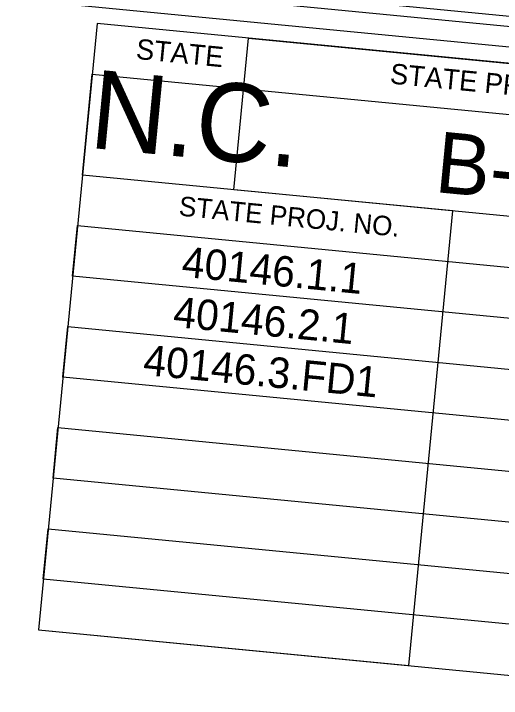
# Model space of a CAD drawing. Extents: x 2060574 to 2063008, y 912203 to 913082.
# Drawn here: x 2061449.3 to 2061521.3, y 912882.4 to 912983.6 of the extents above; entities that cross this region are included whole.
import ezdxf

# ---------------------------------------------------------------- set-up
doc = ezdxf.new("R2010")
doc.units = 0
for name, color, linetype in [('Sheet Data Field CELL', 7, 'Continuous'), ('Sheet Plot Border Inside CELL', 7, 'Continuous'), ('Sheet Title CELL', 7, 'Continuous')]:
    doc.layers.add(name, color=color, linetype=linetype)

msp = doc.modelspace()

# ---------------------------------------------------------------- linework, layer by layer
at = {"layer": 'Sheet Plot Border Inside CELL'}
msp.add_lwpolyline([(2060583.16, 912437.96), (2061578.42, 912341.76), (2061639.33, 912971.88), (2060644.07, 913068.09)], close=True, dxfattribs=at)
at = {"layer": 'Sheet Title CELL'}
for points in [[(2061625.75, 912971.65), (2060741.86, 913057.1)], [(2061622.47, 912968.96), (2060774.43, 913050.93)], [(2061625.82, 912966.23), (2061461.59, 912982.1), (2061452.93, 912892.52), (2061507.66, 912887.22), (2061514.16, 912954.41), (2061481.82, 912957.54), (2061483.99, 912979.94), (2061581.04, 912970.55)], [(2061623.66, 912943.83), (2061459.42, 912959.71), (2061460.87, 912974.64), (2061625.1, 912958.76)], [(2061622.22, 912928.9), (2061457.98, 912944.77), (2061458.7, 912952.24), (2061622.94, 912936.36)], [(2061620.77, 912913.97), (2061456.54, 912929.85), (2061457.26, 912937.31), (2061621.49, 912921.44)], [(2061619.33, 912899.04), (2061455.1, 912914.91), (2061455.82, 912922.38), (2061620.05, 912906.51)], [(2061617.89, 912884.11), (2061453.65, 912899.99), (2061454.37, 912907.45), (2061618.61, 912891.57)], [(2061452.93, 912892.52), (2061617.16, 912876.65)]]:
    msp.add_lwpolyline(points, dxfattribs=at)

# ---------------------------------------------------------------- texts
at = {"layer": 'Sheet Data Field CELL'}
for s, height, p in [('B-4944', 9, (2061511.34, 912957.22)), ('40146.1.1', 4.5, (2061473.98, 912944.7)), ('40146.2.1', 4.5, (2061472.72, 912937.29)), ('40146.3.FD1', 4.5, (2061468.29, 912930.19))]:
    msp.add_text(s, height=height, rotation=354.4787, dxfattribs=at).set_placement(p)
at = {"layer": 'Sheet Title CELL'}
for s, height, p in [('STATE', 3, (2061467.26, 912976.89)), ('STATE PROJECT REFERENCE NO.', 2.9999, (2061504.8, 912973.25)), ('N.C.', 11.61, (2061460.27, 912963.76)), ('STATE PROJ. NO.', 2.88, (2061473.59, 912953.73))]:
    msp.add_text(s, height=height, rotation=354.4787, dxfattribs=at).set_placement(p)

doc.saveas('drawing.dxf')
